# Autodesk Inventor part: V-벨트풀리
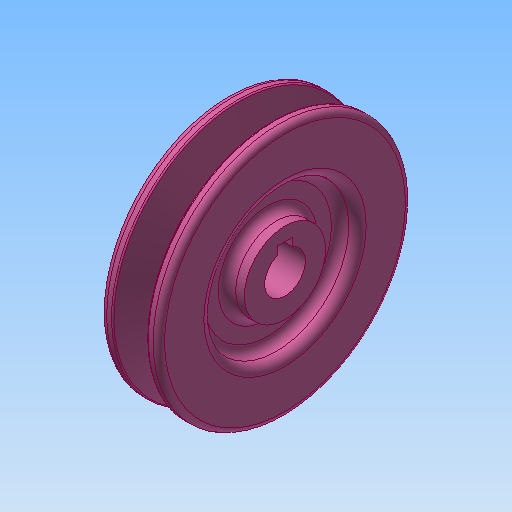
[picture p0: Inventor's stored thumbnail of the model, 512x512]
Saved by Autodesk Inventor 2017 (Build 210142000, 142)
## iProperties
Created: 2019-09
Part Number: V-벨트풀리
Material: 알루미늄 6061
Document SubType Name: Modeling
Designer: mduedu
Density: 1 g/cm^3
Appearance: 분홍색
Author: mduedu
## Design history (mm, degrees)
sketch "스케치1"
  geometry: L1 (-10, 0)-(10, 0); L2 (10, 0)-(10, 43.5); L3 (10, 43.5)-(-10, 43.5); L4 (-10, 43.5)-(-10, 0); L5 (0, 0)-(0, 43.5); L6 (-5.976, 43.5)-(-2.154, 31); L7 (-2.154, 31)-(2.154, 31); L8 (2.154, 31)-(5.976, 43.5); L9 (-10, 39)-(10, 39); 3 further points
  constraints: 18 end point, 8 point on line, 3 perpendicular, 2 midpoint, 2 parallel, 1 coincident, 1 horizontal, 1 other
  dimensions: "d0" = 87 diameter of L3 L1; "d3" = 12.5 distance between parallel lines of L7 L3; "d4" = 34 deg angle of L8 L6; "d5" = 20 distance between parallel lines of L2 L4; "d6" = 8 distance between parallel lines of L9 L7; "d7" = 9.2 distance of point (4.6, 39) point (-4.6, 39)
revolve "회전1" sketch "스케치1" stored, may be unused: angle "d8" = 90 deg
sketch "스케치2"
  geometry: C1 r 14 at (0, 0); C2 r 25 at (0, 0); 1 further point
  constraints: 2 centre point, 2 coincident
  dimensions: "d9" = 28 diameter of C1; "d10" = 50 diameter of C2
extrude "돌출1" cut sketch "스케치2" distance "d11" = 6; taper "d12" = 0 deg
fillet "모깎기1" dims "d13" = 3
fillet "모깎기2" dims "d14" = 3
fillet "모깎기3" dims "d15" = 0.5, "d16" = 1, "d17" = 2
sketch "스케치3"
  geometry: L1 (-2.5, 6.538)-(2.5, 6.538); L2 (2.5, 6.538)-(2.5, 9.3); L3 (2.5, 9.3)-(-2.5, 9.3); L4 (-2.5, 9.3)-(-2.5, 6.538); A1 r 7 centre (0, 0) between (-2.5, 6.538) and (2.5, 6.538); 1 further point
  constraints: 8 end point, 2 parallel, 2 point on circle, 1 centre point, 1 coincident, 1 horizontal, 1 perpendicular
  dimensions: "d18" = 14 diameter of A1; "d20" = 5 distance of L2.end L3.end; "d21" = 16.3 dimension on A1 L3
extrude "돌출2" cut sketch "스케치3" stored distance "d22" = 6; taper "d23" = 0 deg
node "솔리드1"
mirror "대칭1"
